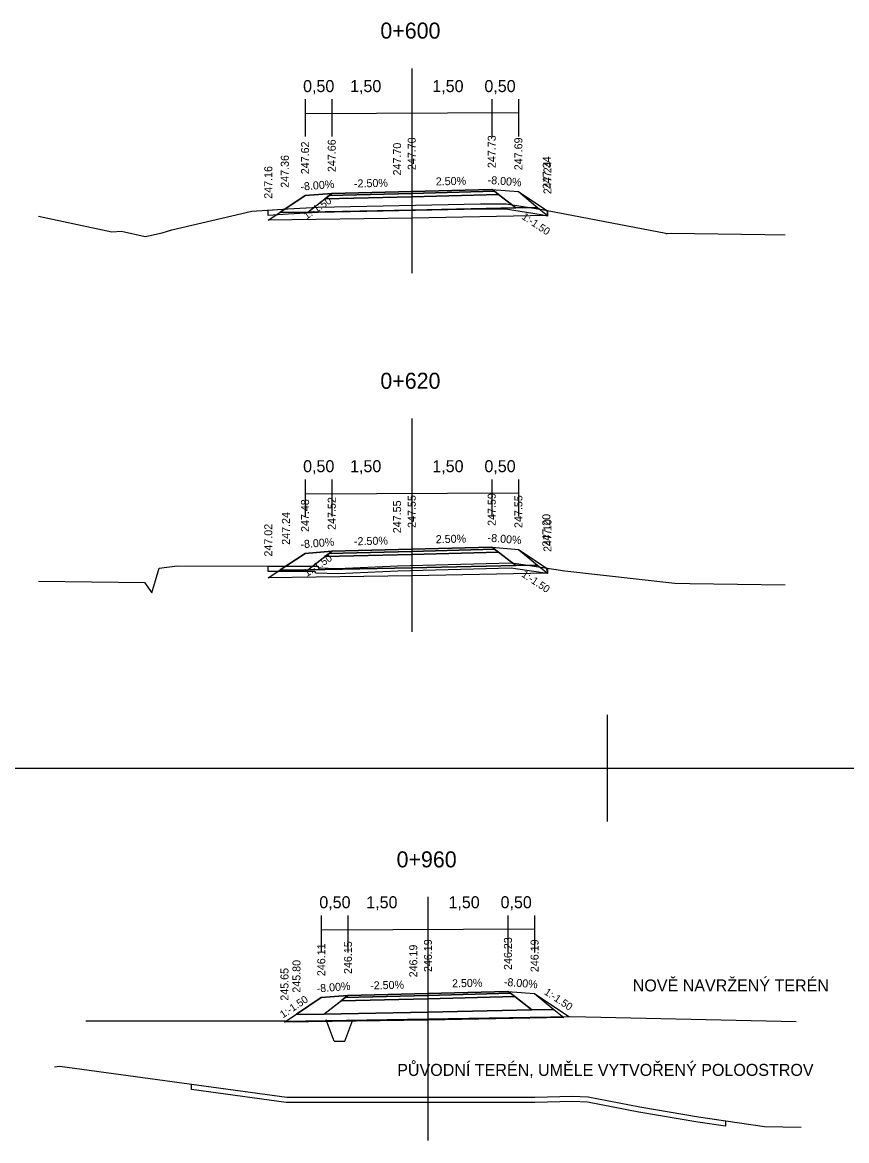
# Model space of a CAD drawing. Extents: x -552501 to -552394, y -1029983 to -1029892.
# Drawn here: x -552468.72 to -552453.26, y -1029959.73 to -1029938.77 of the extents above; entities that cross this region are included whole.
import ezdxf

# ---------------------------------------------------------------- set-up
doc = ezdxf.new("R2010")
doc.units = 0
for name, color, linetype in [('1', 7, 'Continuous'), ('16', 7, 'Continuous'), ('60', 7, 'Continuous'), ('9', 7, 'Continuous'), ('FORMATY', 7, 'Continuous'), ('Implicitní', 7, 'Continuous'), ('rámeček', 7, 'Continuous')]:
    doc.layers.add(name, color=color, linetype=linetype)

msp = doc.modelspace()

# ---------------------------------------------------------------- linework, layer by layer
for p, q in [((-552463.795, -1029957.489), (-552467.531, -1029957.489)), ((-552462.877, -1029957.867), (-552463.027, -1029957.467)), ((-552462.677, -1029957.867), (-552462.527, -1029957.467)), ((-552462.877, -1029957.867), (-552462.677, -1029957.867))]:
    msp.add_line(p, q)
for points in [[(-552464.11, -1029942.48), (-552463.8, -1029942.274), (-552463.42, -1029942.02), (-552462.92, -1029941.98), (-552461.42, -1029941.943), (-552459.92, -1029941.905), (-552459.42, -1029941.945), (-552458.888, -1029942.3), (-552458.874, -1029942.393)], [(-552468.42, -1029942.408), (-552467.041, -1029942.701), (-552466.86, -1029942.69), (-552466.416, -1029942.789), (-552466.354, -1029942.777), (-552466.1, -1029942.718), (-552465.917, -1029942.66), (-552464.416, -1029942.315), (-552463.741, -1029942.27), (-552463.177, -1029942.24), (-552460.129, -1029942.177), (-552459.652, -1029942.176), (-552458.973, -1029942.283), (-552456.658, -1029942.726), (-552456.657, -1029942.733), (-552456.657, -1029942.732), (-552456.637, -1029942.733), (-552456.632, -1029942.729), (-552456.558, -1029942.724), (-552454.8, -1029942.749), (-552454.42, -1029942.753)], [(-552464.11, -1029949.184), (-552463.779, -1029948.964), (-552463.42, -1029948.724), (-552462.92, -1029948.684), (-552461.42, -1029948.647), (-552459.92, -1029948.609), (-552459.42, -1029948.649), (-552458.896, -1029948.998), (-552458.874, -1029949.097)], [(-552468.42, -1029949.245), (-552466.43, -1029949.269), (-552466.291, -1029949.464), (-552466.159, -1029949.003), (-552465.821, -1029948.959), (-552463.189, -1029948.965), (-552463.162, -1029948.996), (-552462.808, -1029949.01), (-552461.686, -1029948.955), (-552459.549, -1029948.902), (-552459.458, -1029948.913), (-552458.547, -1029949.051), (-552456.489, -1029949.285), (-552456.202, -1029949.288), (-552454.42, -1029949.313)], [(-552463.781, -1029957.489), (-552463.581, -1029957.356), (-552463.116, -1029957.046), (-552462.616, -1029957.006), (-552461.116, -1029956.969), (-552459.616, -1029956.931), (-552459.116, -1029956.971), (-552458.472, -1029957.4)], [(-552463.795, -1029957.489), (-552458.437, -1029957.4), (-552454.211, -1029957.497)], [(-552468.116, -1029958.347), (-552468.017, -1029958.332), (-552463.765, -1029958.914), (-552463.597, -1029958.915), (-552459.113, -1029958.914), (-552458.407, -1029958.898), (-552458.111, -1029958.905), (-552457.145, -1029959.097), (-552456.043, -1029959.285), (-552454.804, -1029959.465), (-552454.116, -1029959.476)]]:
    msp.add_lwpolyline(points)
for points in [[(-552462.92, -1029941.98), (-552463.42, -1029942.02), (-552463.885, -1029942.33), (-552463.37, -1029942.33)], [(-552463.37, -1029942.33), (-552463.048, -1029942.08), (-552461.42, -1029942.043), (-552459.792, -1029941.999), (-552459.47, -1029942.249), (-552461.42, -1029942.293)], [(-552461.42, -1029941.983), (-552462.971, -1029942.02), (-552463.048, -1029942.08), (-552461.42, -1029942.043), (-552459.792, -1029941.999), (-552459.869, -1029941.939), (-552461.42, -1029941.983), (-552459.869, -1029941.939), (-552459.92, -1029941.905), (-552461.42, -1029941.943), (-552462.92, -1029941.98), (-552462.971, -1029942.02)], [(-552463.048, -1029942.08), (-552462.971, -1029942.02), (-552461.42, -1029941.983), (-552459.869, -1029941.939), (-552459.792, -1029941.999), (-552461.42, -1029942.043)], [(-552459.92, -1029941.905), (-552459.42, -1029941.945), (-552459.059, -1029942.243), (-552459.47, -1029942.249), (-552459.792, -1029941.999), (-552459.869, -1029941.939)], [(-552464.11, -1029942.295), (-552463.741, -1029942.27), (-552463.177, -1029942.24), (-552460.129, -1029942.177), (-552459.652, -1029942.176), (-552458.973, -1029942.283), (-552458.874, -1029942.302), (-552458.874, -1029942.404), (-552458.991, -1029942.382), (-552459.659, -1029942.276), (-552460.128, -1029942.277), (-552463.173, -1029942.34), (-552463.735, -1029942.369), (-552464.11, -1029942.395)], [(-552464.11, -1029942.48), (-552463.885, -1029942.33), (-552463.37, -1029942.33), (-552461.42, -1029942.293), (-552459.47, -1029942.249), (-552459.059, -1029942.243), (-552458.874, -1029942.393), (-552461.42, -1029942.443)], [(-552462.92, -1029948.684), (-552463.42, -1029948.724), (-552463.885, -1029949.034), (-552463.37, -1029949.034)], [(-552463.37, -1029949.034), (-552463.048, -1029948.784), (-552461.42, -1029948.747), (-552459.792, -1029948.703), (-552459.47, -1029948.953), (-552461.42, -1029948.997)], [(-552461.42, -1029948.687), (-552462.971, -1029948.724), (-552463.048, -1029948.784), (-552461.42, -1029948.747), (-552459.792, -1029948.703), (-552459.869, -1029948.643), (-552461.42, -1029948.687), (-552459.869, -1029948.643), (-552459.92, -1029948.609), (-552461.42, -1029948.647), (-552462.92, -1029948.684), (-552462.971, -1029948.724)], [(-552463.048, -1029948.784), (-552462.971, -1029948.724), (-552461.42, -1029948.687), (-552459.869, -1029948.643), (-552459.792, -1029948.703), (-552461.42, -1029948.747)], [(-552459.92, -1029948.609), (-552459.42, -1029948.649), (-552459.059, -1029948.947), (-552459.47, -1029948.953), (-552459.792, -1029948.703), (-552459.869, -1029948.643)], [(-552464.11, -1029948.963), (-552463.189, -1029948.965), (-552463.162, -1029948.996), (-552462.808, -1029949.01), (-552461.686, -1029948.955), (-552459.549, -1029948.902), (-552459.458, -1029948.913), (-552458.874, -1029949.002), (-552458.874, -1029949.103), (-552459.471, -1029949.012), (-552459.554, -1029949.002), (-552461.682, -1029949.055), (-552462.807, -1029949.11), (-552463.209, -1029949.094), (-552463.235, -1029949.065), (-552464.11, -1029949.063)], [(-552464.11, -1029949.184), (-552463.885, -1029949.034), (-552463.37, -1029949.034), (-552461.42, -1029948.997), (-552459.47, -1029948.953), (-552459.059, -1029948.947), (-552458.874, -1029949.097), (-552461.42, -1029949.147)], [(-552461.116, -1029957.009), (-552462.667, -1029957.046), (-552462.744, -1029957.106), (-552461.116, -1029957.069), (-552459.488, -1029957.025), (-552459.565, -1029956.965), (-552461.116, -1029957.009), (-552459.565, -1029956.965), (-552459.616, -1029956.931), (-552461.116, -1029956.969), (-552462.616, -1029957.006), (-552462.667, -1029957.046)], [(-552459.616, -1029956.931), (-552459.116, -1029956.971), (-552458.755, -1029957.269), (-552459.166, -1029957.275), (-552459.488, -1029957.025), (-552459.565, -1029956.965)], [(-552462.616, -1029957.006), (-552463.116, -1029957.046), (-552463.581, -1029957.356), (-552463.066, -1029957.356)], [(-552463.066, -1029957.356), (-552462.744, -1029957.106), (-552461.116, -1029957.069), (-552459.488, -1029957.025), (-552459.166, -1029957.275), (-552461.116, -1029957.319)], [(-552462.744, -1029957.106), (-552462.667, -1029957.046), (-552461.116, -1029957.009), (-552459.565, -1029956.965), (-552459.488, -1029957.025), (-552461.116, -1029957.069)], [(-552463.806, -1029957.506), (-552463.581, -1029957.356), (-552463.066, -1029957.356), (-552461.116, -1029957.319), (-552459.166, -1029957.275), (-552458.755, -1029957.269), (-552458.57, -1029957.419), (-552461.116, -1029957.469)], [(-552465.551, -1029958.67), (-552463.765, -1029958.914), (-552463.597, -1029958.915), (-552459.113, -1029958.914), (-552458.407, -1029958.898), (-552458.111, -1029958.905), (-552457.145, -1029959.097), (-552456.043, -1029959.285), (-552455.534, -1029959.359), (-552455.534, -1029959.46), (-552456.058, -1029959.384), (-552457.163, -1029959.196), (-552458.122, -1029959.005), (-552458.407, -1029958.998), (-552459.112, -1029959.014), (-552463.597, -1029959.015), (-552463.773, -1029959.014), (-552465.551, -1029958.771)]]:
    msp.add_lwpolyline(points, close=True)
at = {"layer": '60'}
for p, q in [((-552461.42, -1029939.638), (-552461.42, -1029943.477)), ((-552461.42, -1029946.2), (-552461.42, -1029950.192)), ((-552461.116, -1029955.161), (-552461.116, -1029959.728))]:
    msp.add_line(p, q, dxfattribs=at)
at = {"layer": '9'}
for p, q in [((-552463.42, -1029940.216), (-552463.42, -1029940.914)), ((-552462.92, -1029940.216), (-552462.92, -1029940.914)), ((-552461.42, -1029940.216), (-552461.42, -1029941.716)), ((-552459.92, -1029940.216), (-552459.92, -1029940.914)), ((-552459.42, -1029940.216), (-552459.42, -1029940.914)), ((-552463.42, -1029947.338), (-552463.42, -1029948.036)), ((-552462.92, -1029947.338), (-552462.92, -1029948.036)), ((-552461.42, -1029947.338), (-552461.42, -1029948.838)), ((-552459.92, -1029947.338), (-552459.92, -1029948.036)), ((-552459.42, -1029947.338), (-552459.42, -1029948.036)), ((-552463.116, -1029955.509), (-552463.116, -1029956.206)), ((-552462.616, -1029955.509), (-552462.616, -1029956.206)), ((-552461.116, -1029955.509), (-552461.116, -1029957.009)), ((-552459.616, -1029955.509), (-552459.616, -1029956.206)), ((-552459.116, -1029955.509), (-552459.116, -1029956.206))]:
    msp.add_line(p, q, dxfattribs=at)
at = {"layer": 'FORMATY'}
for p, q in [((-552457.755, -1029951.75), (-552457.755, -1029953.75)), ((-552458.755, -1029952.75), (-552456.755, -1029952.75))]:
    msp.add_line(p, q, dxfattribs=at)
at = {"layer": 'Implicitní'}
for p, q in [((-552463.41, -1029940.484), (-552459.42, -1029940.466)), ((-552463.41, -1029947.606), (-552459.42, -1029947.588)), ((-552463.106, -1029955.776), (-552459.116, -1029955.759))]:
    msp.add_line(p, q, dxfattribs=at)
at = {"layer": 'rámeček'}
for p, q in [((-552457.755, -1029952.25), (-552457.755, -1029952.75)), ((-552499.755, -1029952.75), (-552394.755, -1029952.75)), ((-552499.755, -1029952.75), (-552394.755, -1029952.75)), ((-552499.755, -1029952.75), (-552394.755, -1029952.75))]:
    msp.add_line(p, q, dxfattribs=at)

# ---------------------------------------------------------------- texts
for rotation, p in [(33.6902, (-552463.393, -1029942.471)), (326.3098, (-552459.37, -1029942.447)), (33.6902, (-552463.383, -1029949.168)), (326.3098, (-552459.374, -1029949.148)), (326.3098, (-552458.948, -1029956.975)), (33.6902, (-552463.834, -1029957.439))]:
    msp.add_text('1:-1.50', height=0.14, rotation=rotation).set_placement(p)
at = {"layer": '1'}
for s, p in [('0+600', (-552462.008, -1029939.079)), ('0+620', (-552462.008, -1029945.64)), ('0+960', (-552461.704, -1029954.608))]:
    msp.add_text(s, height=0.3, dxfattribs=at).set_placement(p)
at = {"layer": '16'}
for s, p in [('0,50', (-552463.457, -1029940.081)), ('1,50', (-552462.576, -1029940.081)), ('1,50', (-552461.034, -1029940.081)), ('0,50', (-552460.057, -1029940.081)), ('0,50', (-552463.457, -1029947.203)), ('1,50', (-552462.576, -1029947.203)), ('1,50', (-552461.034, -1029947.203)), ('0,50', (-552460.057, -1029947.203)), ('0,50', (-552463.153, -1029955.374)), ('1,50', (-552462.273, -1029955.374)), ('1,50', (-552460.731, -1029955.374)), ('0,50', (-552459.754, -1029955.374)), ('NOVĚ NAVRŽENÝ TERÉN', (-552457.275, -1029956.933)), ('PŮVODNÍ TERÉN, UMĚLE VYTVOŘENÝ POLOOSTROV', (-552461.692, -1029958.515))]:
    msp.add_text(s, height=0.225, dxfattribs=at).set_placement(p)
for s, rotation, p in [('247.62', 90, (-552463.345, -1029941.62)), ('247.66', 90, (-552462.845, -1029941.58)), ('247.70', 90, (-552461.345, -1029941.543)), ('247.73', 90, (-552459.845, -1029941.505)), ('247.69', 90, (-552459.345, -1029941.545)), ('247.70', 90, (-552461.62, -1029941.643)), ('247.36', 90, (-552463.725, -1029941.874)), ('247.34', 90, (-552458.813, -1029941.9)), ('247.24', 90, (-552458.799, -1029941.993)), ('247.16', 90, (-552464.035, -1029942.08)), ('-8.00%', 4.5739, (-552463.501, -1029941.927)), ('-2.50%', 1.4321, (-552462.501, -1029941.87)), ('2.50%', 1.4321, (-552460.967, -1029941.831)), ('-8.00%', 355.4261, (-552460.001, -1029941.799)), ('247.48', 90, (-552463.345, -1029948.324)), ('247.52', 90, (-552462.845, -1029948.284)), ('247.55', 90, (-552461.345, -1029948.247)), ('247.59', 90, (-552459.845, -1029948.209)), ('247.55', 90, (-552459.345, -1029948.249)), ('247.55', 90, (-552461.62, -1029948.347)), ('247.24', 90, (-552463.704, -1029948.564)), ('247.20', 90, (-552458.821, -1029948.598)), ('247.10', 90, (-552458.799, -1029948.697)), ('247.02', 90, (-552464.035, -1029948.784)), ('-8.00%', 4.5739, (-552463.501, -1029948.631)), ('-2.50%', 1.4321, (-552462.501, -1029948.574)), ('2.50%', 1.4321, (-552460.967, -1029948.535)), ('-8.00%', 355.4261, (-552460.001, -1029948.503)), ('246.11', 90, (-552463.041, -1029956.646)), ('246.15', 90, (-552462.541, -1029956.606)), ('246.19', 90, (-552461.316, -1029956.669)), ('246.19', 90, (-552461.041, -1029956.569)), ('246.23', 90, (-552459.541, -1029956.531)), ('246.19', 90, (-552459.041, -1029956.571)), ('245.65', 90, (-552463.731, -1029957.106)), ('245.80', 90, (-552463.506, -1029956.956)), ('-2.50%', 1.4321, (-552462.198, -1029956.896)), ('2.50%', 1.4321, (-552460.663, -1029956.857)), ('-8.00%', 355.4261, (-552459.697, -1029956.825)), ('-8.00%', 4.5739, (-552463.197, -1029956.953))]:
    msp.add_text(s, height=0.15, rotation=rotation, dxfattribs=at).set_placement(p)

doc.saveas('drawing.dxf')
